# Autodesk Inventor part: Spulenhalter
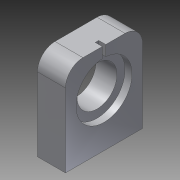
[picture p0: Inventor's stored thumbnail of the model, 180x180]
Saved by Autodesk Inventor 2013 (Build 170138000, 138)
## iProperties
Created: 2012-07
Part Number: Spulenhalter
Material: Aluminium 6061
Document SubType Name: Modeling
Designer: rYan
Density: 2.71 g/cm^3
Mass: 12.4241 g
Surface Area: 26.6862 cm^2
Volume: 4.58452 cm^3
Author: rYan
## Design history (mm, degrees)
sketch "Skizze1"
  geometry: L1 (0, -4)-(0, 22); L2 (0, 22)-(-8, 22); L3 (-8, 22)-(-8, -4); L4 (-8, -4)-(0, -4); L5 (-9.6, 0)-(1.6, 0) reference; L6 (0, -9.2)-(0, 27.2) reference
  constraints: 8 end point, 2 parallel, 1 collinear, 1 vertical
  dimensions: "d2" = 8 distance of L1.end L2.end; "d30" = 26 distance of L1.start L1.end; "d43" = 4 distance between parallel lines of L4 L5
extrude "Extrusion1" new body sketch "Skizze1" distance "d5" = 22; taper "d6" = 0 deg
sketch "Skizze2"
  geometry: L1 (0, 0)-(0, 22) reference; L2 (0, 11)-(26, 11); L3 (26, 0)-(26, 22) reference; L4 (26, 0)-(26, 22) reference; 1 further point
  constraints: 2 end point, 2 midpoint, 1 perpendicular, 1 point on line
  dimensions: "d31" = 15 distance from line of L3 point (11, 11)
hole "Bohrung1" sketch "Skizze2" at (11, 11) diameter "d9" = 11.4; stored, may be unused: countersink angle "d13" = 90 deg, drill point angle "d15" = 118 deg; dims "d10" = 6, "d11" = 16, "d12" = 2, "d14" = 2
sketch "Skizze4"
  geometry: L1 (0, 11)-(8, 11); L2 (0, 0)-(0, 22) reference; L3 (8, 0)-(8, 22) reference; L4 (8, 0)-(0, 0) reference; L5 (8, 0)-(8, 22) reference; L6 (0, 22)-(8, 22) reference; L7 (0, 0)-(0, 22) reference; L8 (4, 22)-(4, 0); 2 further points
  constraints: 4 end point, 4 midpoint, 1 point on line, 1 symmetric about line
  dimensions: "d20" = 10 distance of point (4, 16) point (4, 6)
hole "Bohrung2" sketch "Skizze4" at (4, 6), (4, 16) diameter "d21" = 3.242; stored, may be unused: countersink angle "d25" = 90 deg, drill point angle "d27" = 118 deg; dims "d22" = 6, "d23" = 4, "d24" = 2, "d26" = 7
workplane "Arbeitsebene1"
fillet "Rundung1" dims "d42" = 5
sketch "Sketch6"
  geometry: L1 (-26, 5)-(-26, 17) reference; L2 (0, 0)-(-21, 0) reference; L3 (0, 0)-(0, 22) reference; L4 (-21, 22)-(0, 22) reference; L5 (-26, 11)-(-15, 11); L6 (-26, 11.5)-(-15, 11.5); L7 (-15, 11.5)-(-15, 10.5); L8 (-15, 10.5)-(-26, 10.5); L9 (-26, 10.5)-(-26, 11.5); C1 r 8 at (-15, 11) reference; A1 r 5 centre (-21, 17) between (-21, 22) and (-26, 17) reference; A2 r 5 centre (-21, 5) between (-26, 5) and (-21, 0) reference; 1 further point
  constraints: 10 end point, 3 parallel, 2 midpoint, 1 horizontal, 1 perpendicular, 1 point on line, 1 other
  dimensions: "d44" = 1 distance between parallel lines of L8 L6
extrude "Extrusion2" cut sketch "Sketch6" distance "d46" = 2; taper "d47" = 0 deg
node "Volumenkörper1"
node "Projizierte Kontur1"
node "Projizierte Kontur2"
node "Projected Loop3"
